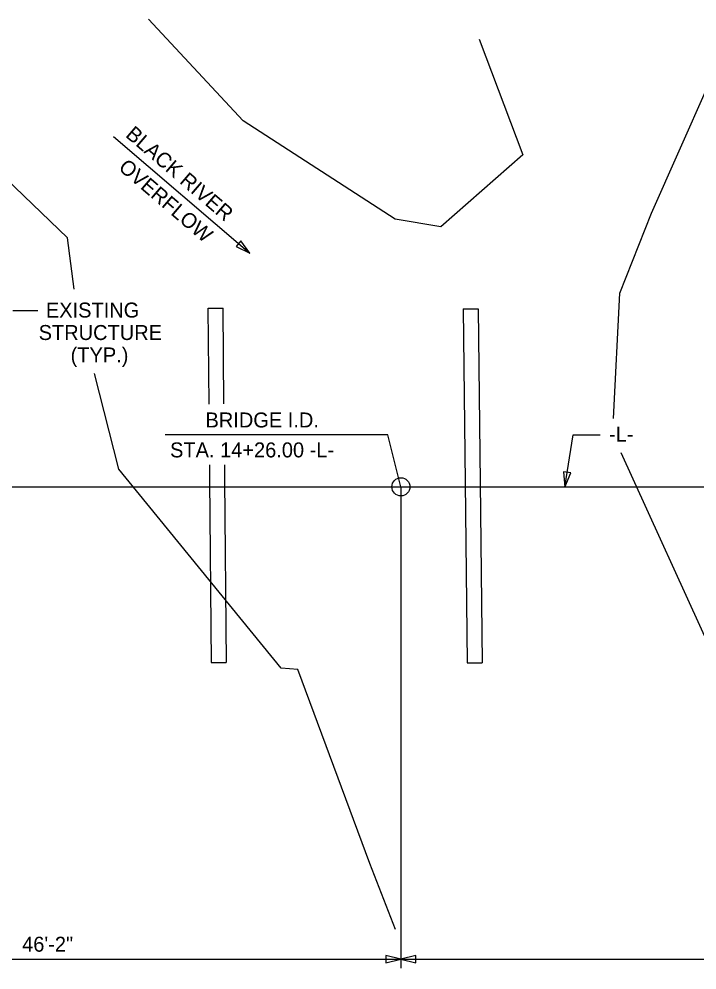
# Model space of a CAD drawing. Extents: x -20 to 509, y -659 to 21.
# Drawn here: x 94.1 to 139.4, y -136.8 to -73.2 of the extents above; entities that cross this region are included whole.
import ezdxf

# ---------------------------------------------------------------- set-up
doc = ezdxf.new("R2010")
doc.units = 0
for name, color, linetype in [('Arrowhead Terminators CELL', 7, 'Continuous'), ('Auto Dimensioning', 7, 'Continuous'), ('Dimension Lines', 7, 'Continuous'), ('Exist Hydro Stream or Body of Water', 7, 'Continuous'), ('Exist Structure Major Bridge Seam', 7, 'Continuous'), ('Prop Horizontal Alignment', 7, 'Continuous')]:
    doc.layers.add(name, color=color, linetype=linetype)

msp = doc.modelspace()

# ---------------------------------------------------------------- linework, layer by layer
at = {"layer": 'Arrowhead Terminators CELL'}
for points in [[(109.48, -88.887), (108.883, -88.047), (108.558, -88.427)], [(130.527, -104.503), (130.933, -103.556), (130.439, -103.476)], [(119.574, -136.045), (118.574, -135.795), (118.574, -136.295)], [(119.574, -136.045), (120.574, -136.295), (120.574, -135.795)]]:
    msp.add_lwpolyline(points, close=True, dxfattribs=at)
at = {"layer": 'Auto Dimensioning'}
for p, q in [((73.409, -136.045), (119.574, -136.045)), ((119.574, -136.045), (165.739, -136.045))]:
    msp.add_line(p, q, dxfattribs=at)
at = {"layer": 'Dimension Lines'}
for p, q in [((100.366, -81.083), (109.48, -88.887)), ((93.629, -92.706), (95.304, -92.706)), ((118.699, -101.022), (103.821, -101.022)), ((119.574, -104.489), (118.699, -101.022)), ((130.527, -104.503), (131.087, -101.022)), ((131.087, -101.022), (132.889, -101.022)), ((119.574, -104.489), (119.574, -136.643))]:
    msp.add_line(p, q, dxfattribs=at)
msp.add_circle((119.574, -104.489), 0.606, dxfattribs=at)
at = {"layer": 'Exist Hydro Stream or Body of Water'}
for points in [[(124.806, -74.584), (127.73, -82.303), (122.246, -87.129), (119.186, -86.616), (109.042, -80.033), (102.703, -73.235)], [(133.79, -99.918), (134.208, -91.542), (136.321, -86.203), (141.964, -73.503)], [(97.738, -91.292), (97.285, -87.847), (89.653, -80.517)], [(119.217, -134.059), (117.508, -129.643), (112.68, -116.682), (111.561, -116.606), (100.727, -103.309), (99.105, -96.92)], [(152.818, -143.472), (145.52, -129.155), (141.407, -120.782), (140.558, -120.72), (140.462, -115.767), (134.29, -102.218)]]:
    msp.add_lwpolyline(points, dxfattribs=at)
at = {"layer": 'Exist Structure Major Bridge Seam'}
for p, q in [((106.699, -92.554), (107.699, -92.554)), ((106.75, -98.961), (106.699, -92.554)), ((107.75, -98.952), (107.699, -92.554)), ((123.743, -92.587), (124.743, -92.587)), ((106.891, -116.216), (107.891, -116.216)), ((124.001, -116.251), (125.001, -116.251))]:
    msp.add_line(p, q, dxfattribs=at)
for points in [[(123.743, -92.587), (123.869, -104.206), (124.001, -116.251)], [(124.743, -92.587), (124.869, -104.206), (125.001, -116.251)], [(106.783, -103.021), (106.791, -104.028), (106.891, -116.216)], [(107.783, -103.013), (107.791, -104.028), (107.891, -116.216)]]:
    msp.add_lwpolyline(points, dxfattribs=at)
at = {"layer": 'Prop Horizontal Alignment'}
msp.add_line((89.68, -104.489), (149.591, -104.489), dxfattribs=at)

# ---------------------------------------------------------------- texts
at = {"layer": 'Dimension Lines'}
for s, p in [('BLACK RIVER', (101.108, -81.06)), ('OVERFLOW', (100.637, -83.256))]:
    msp.add_text(s, height=1, rotation=319.42413, dxfattribs=at).set_placement(p)
for s, p in [('EXISTING', (95.847, -93.179)), ('STRUCTURE', (95.362, -94.679)), ('(TYP.)', (97.5, -96.179)), ('BRIDGE I.D.', (106.515, -100.522)), ('-L-', (133.483, -101.476)), ('STA. 14+26.00 -L-', (104.145, -102.522)), ('46\'-2"', (94.26, -135.545))]:
    msp.add_text(s, height=1, dxfattribs=at).set_placement(p)

doc.saveas('drawing.dxf')
